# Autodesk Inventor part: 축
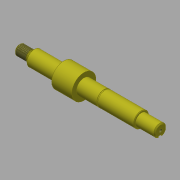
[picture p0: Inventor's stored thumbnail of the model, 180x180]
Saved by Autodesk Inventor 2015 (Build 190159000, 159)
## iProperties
Created: 2016-08
Part Number: 축
Material: 강철, 탄소
Document SubType Name: Modeling
Designer: mduedu
Density: 7.87 g/cm^3
Appearance: 밝은 황색
Author: mduedu
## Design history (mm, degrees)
sketch "스케치1"
  geometry: L1 (-70, 0)-(70, 0); L2 (-70, 0)-(-70, 5); L3 (-70, 5)-(-56, 5); L4 (-56, 5)-(-56, 7.5); L5 (-56, 7.5)-(51, 7.5); L6 (51, 7.5)-(51, 6); L7 (51, 6)-(70, 6); L8 (70, 6)-(70, 0); 2 further points
  constraints: 16 end point, 5 parallel, 2 perpendicular, 1 coincident, 1 horizontal, 1 midpoint
  dimensions: "d0" = 140 distance of L1.start L1.end; "d2" = 14 distance of L2.end L3.end; "d3" = 19 distance of L6.end L7.end; "d4" = 10 diameter of L3 L1; "d5" = 15 diameter of L5 L1; "d6" = 12 diameter of L7 L1
revolve "회전1" sketch "스케치1" stored, may be unused: angle "d7" = 90 deg
sketch "스케치2"
  geometry: L1 (-56, -5)-(-56, 5) reference; L2 (70, -6)-(70, 6) reference; L3 (-56, 0)-(70, 0); L4 (-58, 4.5)-(-58, 5); L5 (-58, 5)-(-56, 5); L6 (-56, 5)-(-56, 4.5); L7 (-58, 4.5)-(-56, 4.5); 1 further point
  constraints: 10 end point, 2 midpoint, 1 parallel, 1 perpendicular, 1 point on line
  dimensions: "d8" = 2 distance of L4.end L5.end; "d10" = 10 diameter of L5 L3; "d11" = 9 diameter of L7 L3
revolve "회전2" sketch "스케치2" stored, may be unused: angle "d12" = 90 deg
node "작업 평면1"
sketch "스케치3"
  geometry: C1 r 12 at (0, 0); 1 further point
  constraints: 1 centre point, 1 coincident
  dimensions: "d15" = 24 diameter of C1
extrude "돌출1" join sketch "스케치3" distance "d16" = 20; taper "d17" = 0 deg
sketch "스케치5"
  geometry: L1 (-70, -5)-(-70, 5) reference; L2 (70, -6)-(70, 6) reference; L3 (-70, 0)-(70, 0); L4 (-6, 7.5)-(51, 7.5) reference; L5 (15.15, 7.5)-(14, 7.5); L6 (14, 7.5)-(14, 7.15); L7 (14, 7.15)-(15.15, 7.15); L8 (15.15, 7.15)-(15.15, 7.5); 1 further point
  constraints: 10 end point, 2 midpoint, 2 parallel, 1 horizontal, 1 perpendicular, 1 point on line
  dimensions: "d19" = 56 distance between parallel lines of L6 L2; "d20" = 1.15 distance between parallel lines of L8 L6; "d21" = 14.3 diameter of L7 L3
revolve "회전3" sketch "스케치5" stored, may be unused: angle "d22" = 90 deg
node "작업 평면3"
sketch "스케치6"
  geometry: L1 (6.5, 2)-(-9.5, 2); L2 (-9.5, 2)-(-9.5, -2); L3 (-9.5, -2)-(6.5, -2); L4 (-9.5, 6)-(-9.5, -6) reference; A1 r 2 centre (6.5, 0) between (6.5, -2) and (6.5, 2); 2 further points
  constraints: 6 end point, 2 midpoint, 2 point on circle, 2 tangent, 1 centre point, 1 horizontal, 1 horizontal alignment, 1 parallel, 1 perpendicular
  dimensions: "d23" = 4 distance between parallel lines of L3 L1; "d62" = 18 dimension on A1 L2
extrude "돌출2" cut sketch "스케치6" distance "d25" = 2.5; taper "d26" = 0 deg
feature "스레드1" dims "d27" = 10, "d28" = 0
chamfer "모따기5" distance "d41" = 0.5; stored, may be unused: second distance "d42" = 2, angle "d43" = 45 deg
chamfer "모따기6" distance "d44" = 0.5; stored, may be unused: second distance "d45" = 2, angle "d46" = 45 deg
chamfer "모따기7" distance "d47" = 1; stored, may be unused: second distance "d48" = 2, angle "d49" = 45 deg
chamfer "모따기8" distance "d50" = 1; stored, may be unused: second distance "d51" = 2, angle "d52" = 45 deg
sketch "스케치8"
  geometry: 1 further point
hole "구멍1" sketch "스케치8" at (2, 3.5) diameter "d53" = 3.242; stored, may be unused: countersink angle "d57" = 90 deg, drill point angle "d59" = 120 deg; dims "d54" = 10, "d55" = 4, "d56" = 2, "d58" = 12
node "솔리드1"
other parameters: "d13" = -44
